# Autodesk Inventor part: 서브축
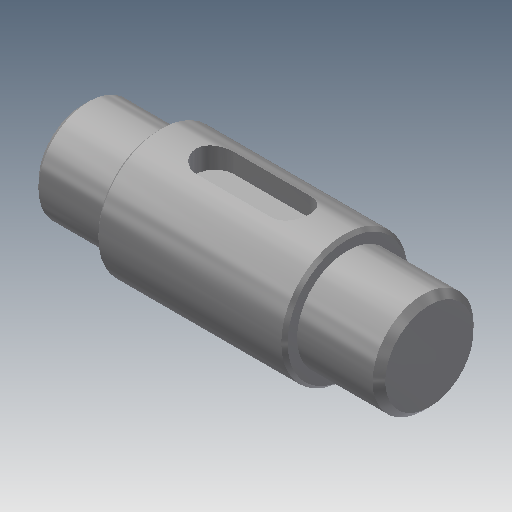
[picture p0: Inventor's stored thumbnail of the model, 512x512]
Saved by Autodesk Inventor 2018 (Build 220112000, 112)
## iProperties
Created: 2019-03
Part Number: 서브축
Material: 강철, 연강
Document SubType Name: Modeling
Designer: mduedu
Density: 1 g/cm^3
Appearance: 강철
Author: mduedu
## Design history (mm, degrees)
sketch "스케치1"
  geometry: L1 (0, 0)-(12, 0); L2 (12, 0)-(12, 8); L3 (12, 8)-(0, 8); L4 (0, 8)-(0, 0); L5 (12, 0)-(42, 0); L6 (42, 0)-(42, 10); L7 (42, 10)-(12, 10); L8 (12, 10)-(12, 0); L9 (42, 0)-(55, 0); L10 (55, 0)-(55, 8); L11 (55, 8)-(42, 8); L12 (42, 8)-(42, 0)
  constraints: 24 end point, 6 parallel, 3 horizontal, 3 perpendicular
  dimensions: "d0" = 16 diameter of L3 L1; "d2" = 20 diameter of L7 L5; "d3" = 16 diameter of L11 L9; "d4" = 12 distance of L2.end L3.end; "d5" = 30 distance of L6.end L7.end; "d6" = 55 distance between parallel lines of L10 L4
revolve "회전1" sketch "스케치1" stored, may be unused: angle "d7" = 90 deg
node "작업 평면1"
sketch "스케치2" dims "d10" = 18
  geometry: L1 (6, -3)-(-6, -3); L2 (-6, -3)-(-6, 3); L3 (-6, 3)-(6, 3); L4 (6, 3)-(6, -3); L5 (15, 10)-(15, -10) reference; 3 further points
  constraints: 8 end point, 2 midpoint, 2 parallel, 2 vertical alignment, 1 horizontal, 1 horizontal alignment, 1 perpendicular, 4 other
  dimensions: "d8" = 6 distance between parallel lines of L3 L1; "d11" = 6 dimension on L5
extrude "돌출1" cut sketch "스케치2" distance "d12" = 3.5; taper "d13" = 0 deg
chamfer "모따기1" distance "d14" = 1; stored, may be unused: second distance "d15" = 2, angle "d16" = 45 deg
chamfer "모따기2" distance "d17" = 0.5; stored, may be unused: second distance "d18" = 2, angle "d19" = 45 deg
node "솔리드1"
